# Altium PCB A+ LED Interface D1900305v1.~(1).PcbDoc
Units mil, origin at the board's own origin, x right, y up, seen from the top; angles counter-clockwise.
Board outline 2700 x 2000 mil, 4 copper layers (Top Layer, InternalPlane1, InternalPlane2, Bottom Layer); 19 components, 34 nets, 90 pads, 10 vias.
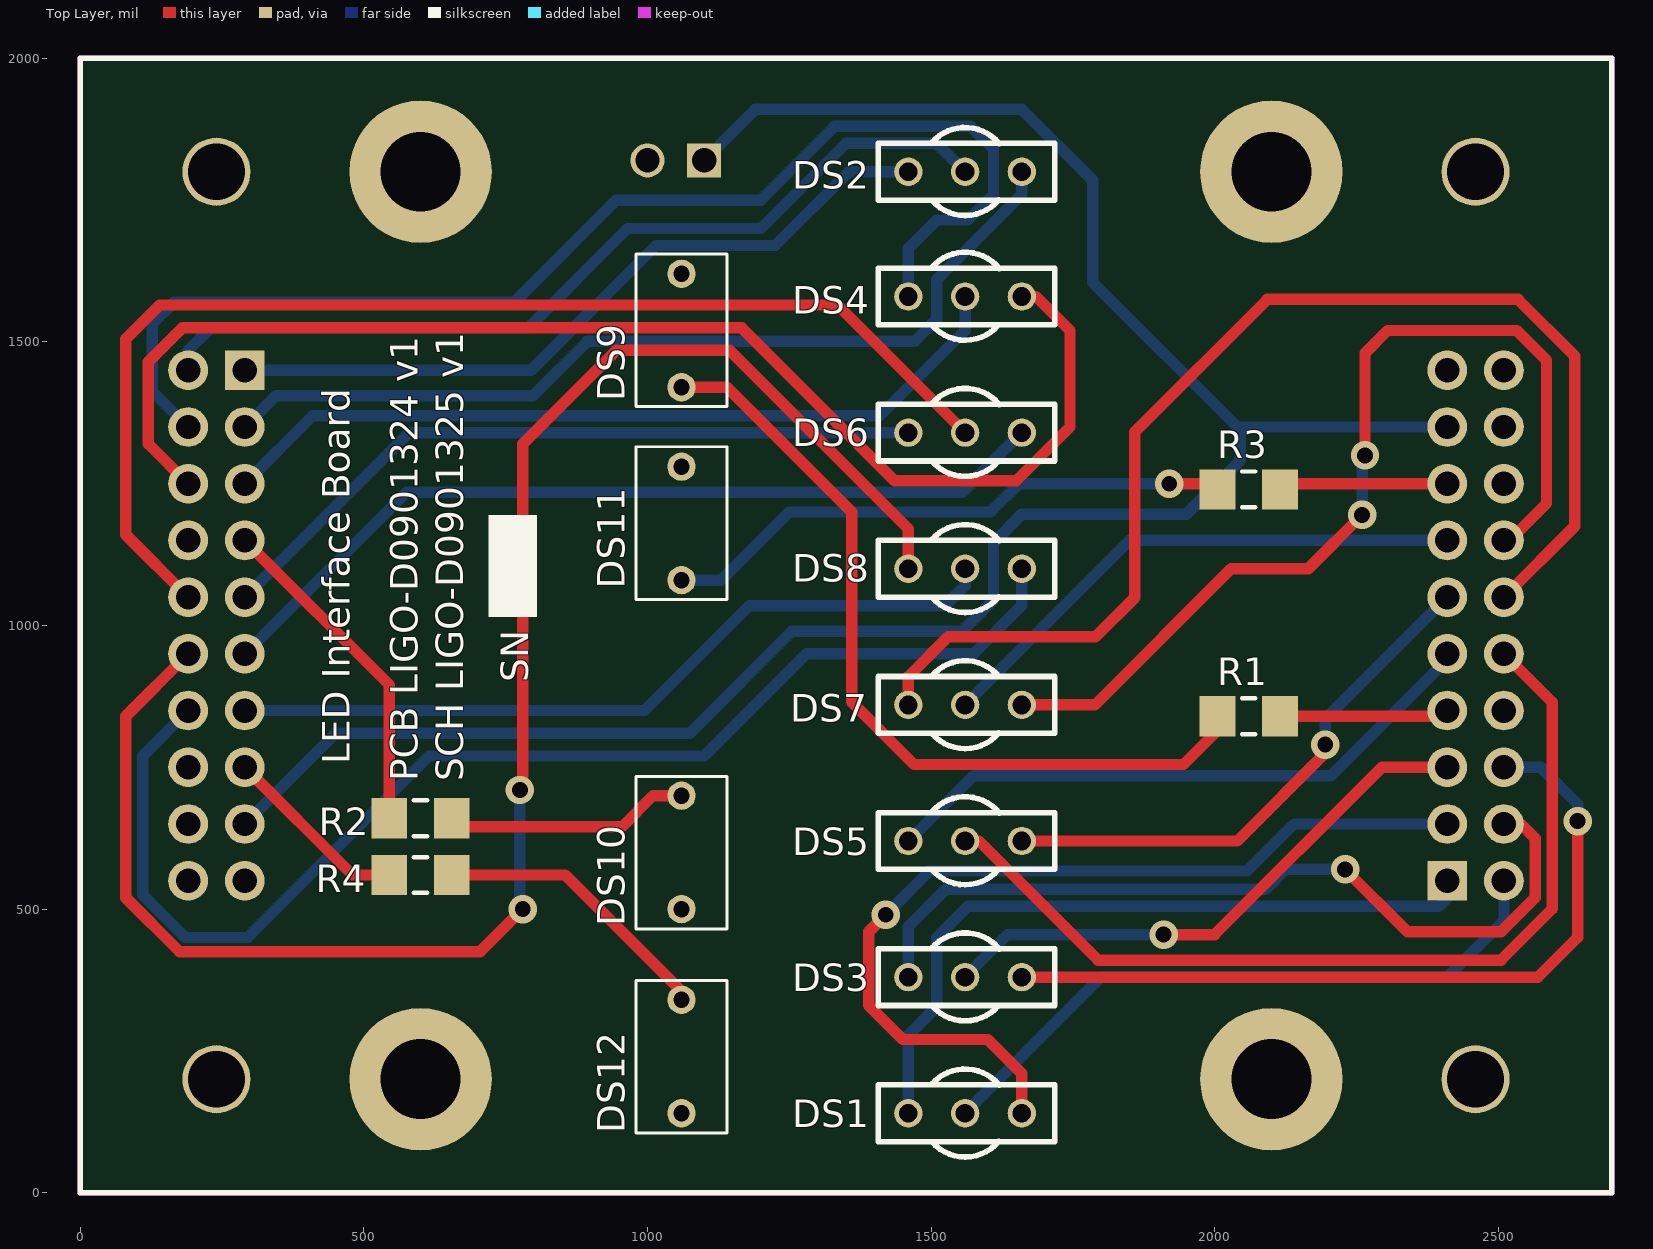
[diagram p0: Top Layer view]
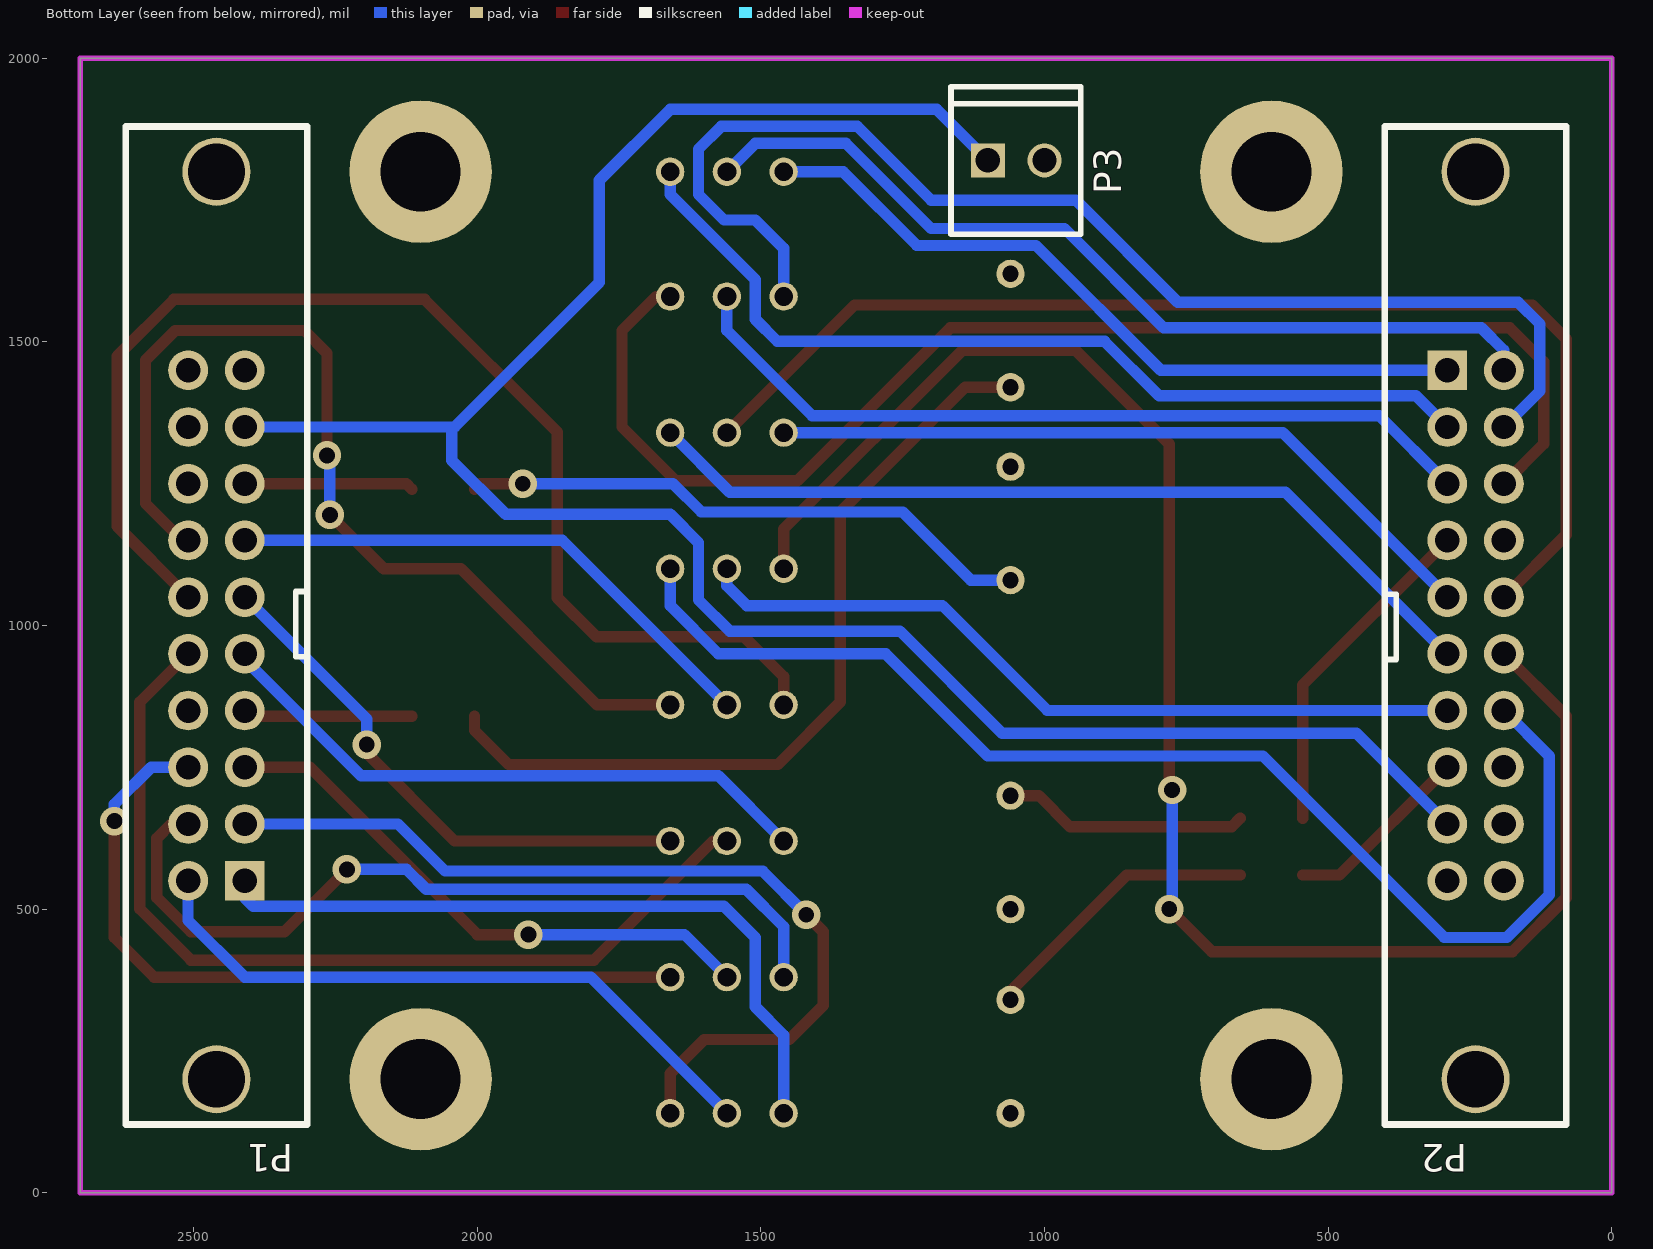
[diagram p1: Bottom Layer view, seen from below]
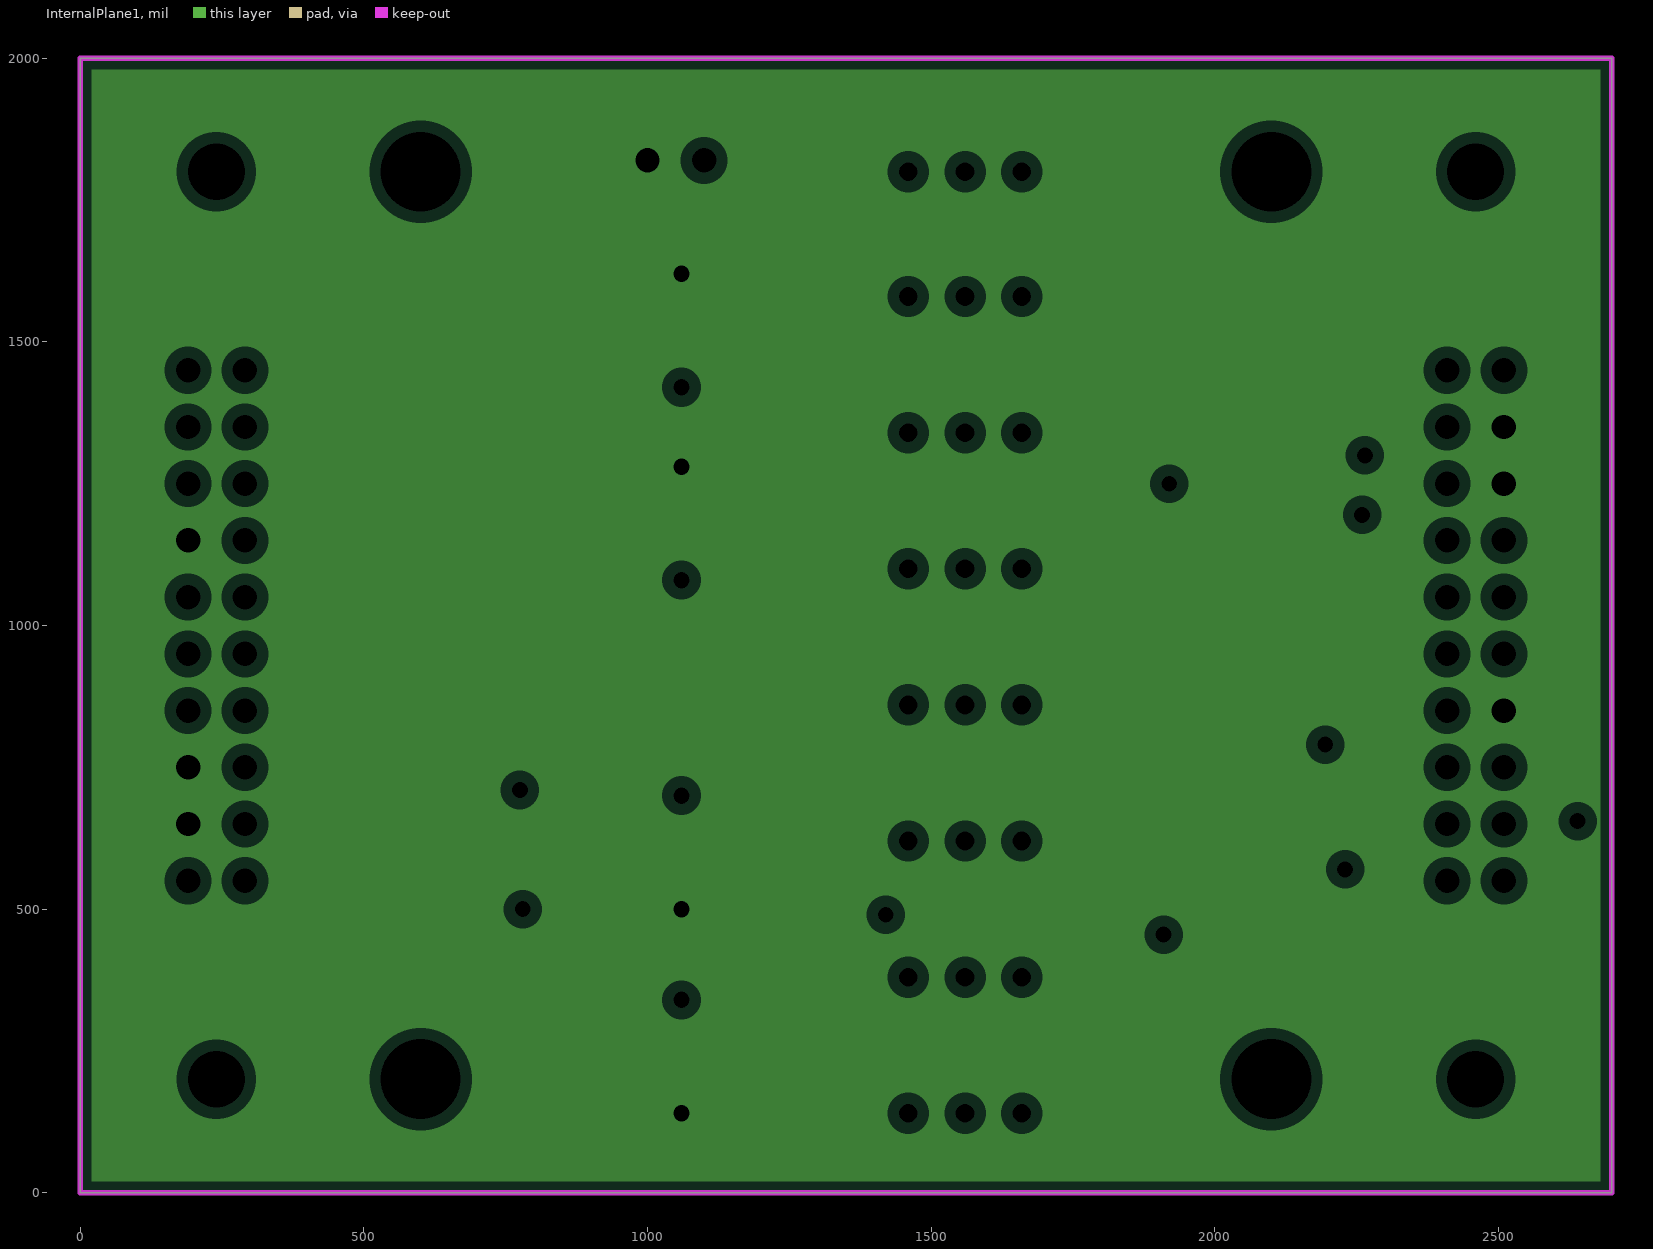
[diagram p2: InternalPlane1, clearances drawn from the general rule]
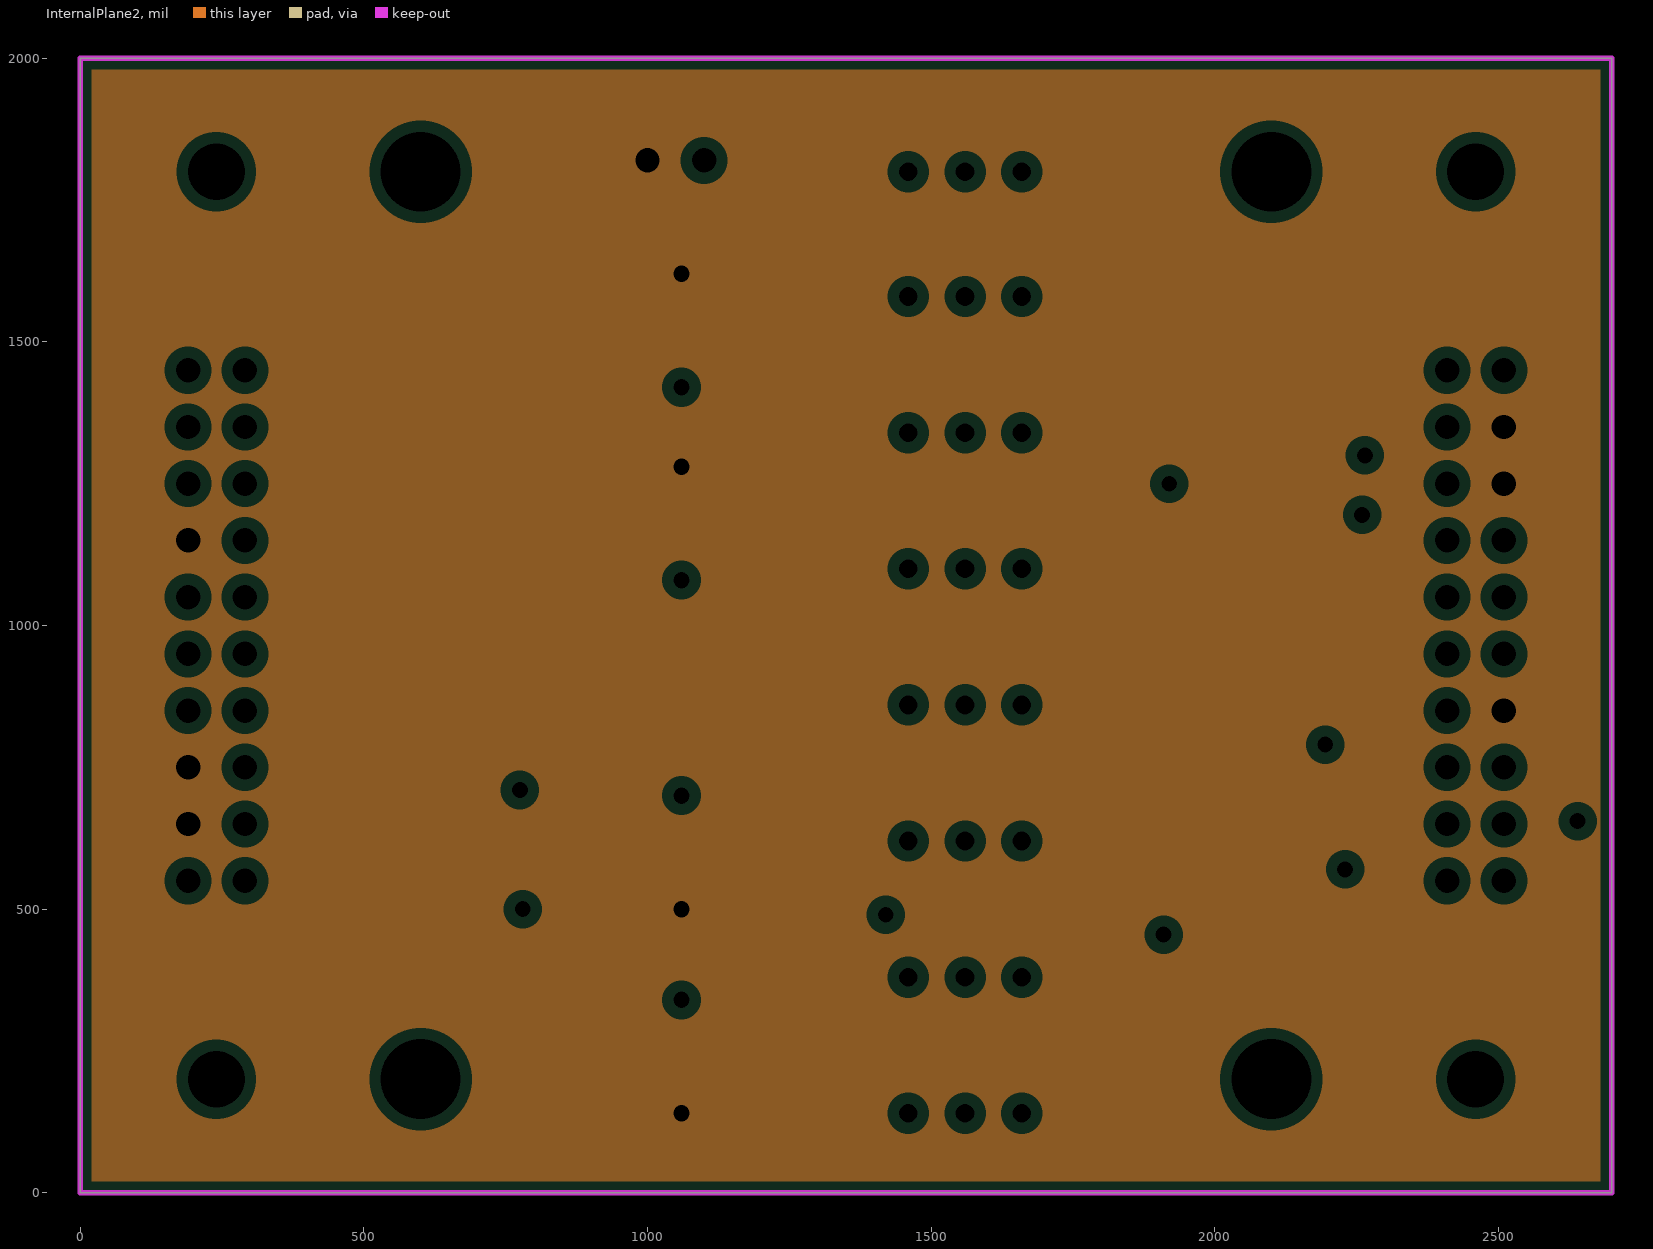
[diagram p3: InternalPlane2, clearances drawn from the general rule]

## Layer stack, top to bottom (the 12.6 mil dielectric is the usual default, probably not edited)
Top Solder: solder mask 0.4, Solder Resist, Dk 3.5
Top Layer: signal copper 1.4
Dielectric1: core 12.6, FR-4, Dk 4.8
InternalPlane1: plane copper 1.4
Dielectric2: prepreg 12.6, FR-4, Dk 4.8
InternalPlane2: plane copper 1.4
Dielectric3: core 12.6, FR-4, Dk 4.8
Bottom Layer: signal copper 1.4
Bottom Solder: solder mask 0.4, Solder Resist, Dk 3.5

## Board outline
0,0 2700,0 2700,2000 0,2000 0,0

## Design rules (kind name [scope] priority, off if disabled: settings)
Clearance [All] p1: gap=10 ignorepadtopadclearanceinfootprint=FALSE except(0: Arc-Hole Track-Hole SMDPad-Hole THPad-Hole Via-Hole Fill-Hole Poly-Hole Region-Hole Text-Hole)
FabricationTestPointUsage TestPointUsage [All] p1: valid=0 allowmultiple=FALSE
FabricationTestpoint Testpoint [All] p1: side=3 testpointundercomponent=TRUE minsize=40 maxsize=100 preferedsize=60 minholesize=0 maxholesize=40 preferedholesize=32 testpointgrid=1 allowsidetop=TRUE allowsidebottom=TRUE usegrid=TRUE gridtolerance=0.01
HoleSize [All] p1: absolutevalues=TRUE maxlimit=300 minlimit=1 maxpercent=80.000 minpercent=20.000
PlaneClearance [All] p1: clearance=20
PlaneConnect [All] p1: planeconnectstyle=Relief reliefexpansion=20 reliefentries=4 reliefconductorwidth=10 reliefairgap=10
PolygonConnect [All] p1: connectstyle=Relief reliefconductorwidth=10 reliefentries=4 polygonreliefangle="90 Angle" airgapwidth=10
RoomDefinition D0901325 [InComponentClass('D0901325')] p1: confinementstyle=ConfineIn formatcopy=TRUE lockcomponents=FALSE outline -40,-35 2735,-35 2735,2030 -40,2030
RoutingVias [All] p1: holewidth=28 width=50 viastyle="Through Hole" minholewidth=28 minwidth=50 maxholewidth=28 maxwidth=50
SolderMaskExpansion [All] p1: expansion=4
Width [All] p1: maxlimit=50 minlimit=10 preferedwidth=20 minimp=50.000000 maximp=50.000000 favimp=50.000000
25 further rules are at their usual default settings.

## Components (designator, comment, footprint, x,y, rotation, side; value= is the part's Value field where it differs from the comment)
DS1 "COM K LED" "COM_CATHODE LED" 1560,140 r90 top
DS2 "COM K LED" "COM_CATHODE LED" 1560,1800 r90 top
DS3 "COM K LED" "COM_CATHODE LED" 1560,380 r90 top
DS4 "COM K LED" "COM_CATHODE LED" 1560,1580 r90 top
DS5 "COM K LED" "COM_CATHODE LED" 1560,620 r90 top
DS6 "COM K LED" "COM_CATHODE LED" 1560,1340 r90 top
DS7 "COM K LED" "COM_CATHODE LED" 1560,860 r90 top
DS8 "COM K LED" "COM_CATHODE LED" 1560,1100 r90 top
DS9 "LED0" RED_led 1060,1420 r0 top
DS10 "LED0" RED_led 1060,700 r180 top
DS11 "LED0" RED_led 1060,1080 r0 top
DS12 "LED0" RED_led 1060,340 r180 top
P1 "Header 20" "IDC 20 _Vertical" 2460,1000 r90 bottom
P2 "Header 20" "IDC 20 _Vertical" 240,1000 r270 bottom
P3 "Molex 2 PIN" "2Pin_Molex 100 mil" 1100,1820 r180 bottom
R1 "1K" 3216[1206] 2060,840 r180 top
R2 "1K" 3216[1206] 600,660 r0 top
R3 "1K" 3216[1206] 2060,1240 r180 top
R4 "1K" 3216[1206] 600,560 r0 top

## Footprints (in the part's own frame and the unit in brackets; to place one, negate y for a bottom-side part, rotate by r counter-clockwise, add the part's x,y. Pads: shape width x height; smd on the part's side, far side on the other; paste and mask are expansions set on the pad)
"2Pin_Molex 100 mil" [mil]
  rect 60x60 hole 43: 1(0,0)
  round 60 hole 43: 2(100,0)
  silkscreen extent -65,-130 164,130
3216[1206] [mm] "Chip Resistor; Body 3.2 x 1.6 mm (LxW typ)"
  rect 1.6x1.8 smd: 1(-1.4,0) 2(1.4,0)
  silkscreen extent -0.3,-0.8 0.3,0.8
"COM_CATHODE LED" [mil]
  round 50 hole 33: 1(0,100) 2(0,0) 3(0,-100)
  silkscreen extent -77,-158 78,153
"IDC 20 _Vertical" [mil]
  round 120 hole 100: 0(-800,0) 0(800,0)
  rect 70x70 hole 43: 1(-450,-50)
  round 70 hole 43: 2(-450,50) 3(-350,-50) 4(-350,50) 5(-250,-50) 6(-250,50) 7(-150,-50) 8(-150,50) 9(-50,-50) 10(-50,50) 11(50,-50) 12(50,50) 13(150,-50) 14(150,50) 15(250,-50) 16(250,50) 17(350,-50) 18(350,50) 19(450,-50) 20(450,50)
  silkscreen extent -880,-160 880,160
RED_led [mil]
  round 50 hole 29: 1(0,0) 2(0,200)
  silkscreen extent -80,-34 80,235

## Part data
DS1 DS2 DS3 DS4 DS5 DS6 DS7 DS8: "Dual Colored LED/ Common Cathode"
DS9 DS10 DS11 DS12: "Typical INFRARED GaAs LED"
P1 P2: "Header, 20-Pin"
P3: library part "Header 2H", "Header, 2-Pin, Right Angle"
R1 R2 R3 R4: library part "Res Semi", "Semiconductor Resistor"

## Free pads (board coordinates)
  round 251 hole 141: 1(600,200) 2(2100,200) 3(2100,1800) 4(600,1800)

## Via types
v1: diameter 50, hole 28, Top Layer to Bottom Layer, 10 vias

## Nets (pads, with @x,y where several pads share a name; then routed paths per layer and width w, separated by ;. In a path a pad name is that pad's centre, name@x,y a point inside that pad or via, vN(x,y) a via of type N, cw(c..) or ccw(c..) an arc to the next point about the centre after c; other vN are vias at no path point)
GND: DS9.2 DS10.2 DS11.2 DS12.2 P1.8 P1.16 P1.18 P2.8 P2.16 P2.18 P3.2
NetDS1_1: DS1.1 P1.1 | length 1289.7
  Bottom Layer w20: DS1.1 1460,277.67 1510,327.67 1510,450 1565,505 2395,505 2410,520 P1.1
NetDS1_2: DS1.2 P1.2 | length 1160.8
  Bottom Layer w20: DS1.2 1800,380 2410,380 2510,480 P1.2
NetDS1_3: DS1.3 P1.3 | length 1618.4
  Top Layer w20: v1(1420,490) 1390,460 1390,330 1450,270 1600,270 1660,210 DS1.3
  Bottom Layer w20: v1(1420,490) 1497,567 2057,567 2140,650 P1.3
NetDS2_1: DS2.1 P2.1 | length 1315
  Bottom Layer w20: P2.1 795,1450 1015,1670 1225,1670 1355,1800 DS2.1
NetDS2_2: DS2.2 P2.2 | length 1576.9
  Bottom Layer w20: P2.2 190,1485 230,1525 790,1525 965,1700 1200,1700 1350,1850 1510,1850 DS2.2
NetDS2_3: DS2.3 P2.3 | length 1620.8
  Bottom Layer w20: P2.3 345,1405 798,1405 894,1501 1471,1501 1510,1540 1510,1610 1660,1760 DS2.3
NetDS3_1: DS3.1 P1.4 | length 1471.6
  Top Layer w20: v1(2230,570) 2340,460 2360,460 ; 2365,460 2505,460 2565,520 2565,625 2540,650 P1.4
  Bottom Layer w20: DS3.1 1460,469 1526,535 2090,535 2125,570 v1(2230,570)
NetDS3_2: DS3.2 P1.5 | length 1003.3
  Top Layer w20: v1(1910,455) 2000,455 2295,750 P1.5
  Bottom Layer w20: DS3.2 1635,455 v1(1910,455)
NetDS3_3: DS3.3 P1.6 | length 1400.9
  Top Layer w20: DS3.3 2570,380 2640,450 v1(2640,655)
  Bottom Layer w20: P1.6 2575,750 2640,685 v1(2640,655)
NetDS4_1: DS4.1 P2.4 | length 2206.5
  Bottom Layer w20: P2.4 126.64,1413.36 126.64,1531.64 165,1570 765,1570 945,1750 1200,1750 1330,1880 1570,1880 1610,1840 1610,1760 1565,1715 1510,1715 1460,1665 DS4.1
NetDS4_2: DS4.2 P2.5 | length 1441.8
  Bottom Layer w20: P2.5 410,1370 1410,1370 1560,1520 DS4.2
NetDS4_3: DS4.3 P2.6 | length 2324.9
  Top Layer w20: P2.6 120,1320 120,1465 180,1525 1166,1525 1436,1255 1650,1255 1745,1350 1745,1520 1685,1580 DS4.3
NetDS5_1: DS5.1 P1.9 | length 1092.5
  Bottom Layer w20: DS5.1 1575,735 2205,735 2410,940 P1.9
NetDS5_2: DS5.2 P1.10 | length 1644.5
  Top Layer w20: DS5.2 1584.38,620 1794.38,410 2505,410 2595,500 2595,865 P1.10
NetDS5_3: DS5.3 P1.11 | length 963.3
  Top Layer w20: DS5.3 2040,620 2195,775 v1(2195,790)
  Bottom Layer w20: v1(2195,790) 2195,835 P1.11
NetDS6_1: DS6.1 P2.9 | length 1290.1
  Bottom Layer w20: P2.9 580,1340 DS6.1
NetDS6_2: DS6.2 P2.10 | length 2098.6
  Top Layer w20: P2.10 80,1160 80,1505 140,1565 1335,1565 DS6.2
NetDS6_3: DS6.3 P2.11 | length 1531.5
  Bottom Layer w20: P2.11 575,1235 1555,1235 DS6.3
NetDS7_1: DS7.1 P1.12 | length 2189.7
  Top Layer w20: DS7.1 1460,910 1530,980 1790,980 1859.02,1049.02 1859.02,1341.02 2093,1575 2535,1575 2635,1475 2635,1175 P1.12
NetDS7_2: DS7.2 P1.13 | length 970.1
  Bottom Layer w20: DS7.2 1850,1150 P1.13
NetDS7_3: DS7.3 P1.14 | length 1752.6
  Top Layer w10: 1985,1060 1989,1060
  Top Layer w20: DS7.3 1789,860 2029,1100 2165,1100 v1(2260,1195) ; v1(2265,1300) 2265,1480 2305,1520 2532.57,1520 2585,1467.57 2585,1215 2520,1150 P1.14 P1.14@2510,1140
  Bottom Layer w20: v1(2260,1195) 2260,1295 v1(2265,1300)
NetDS8_1: DS8.1 P2.12 | length 3018.9
  Top Layer w20: P2.12 80,840 80,520 175,425 705,425 v1(780,500) ; v1(775,710) 780,715 780,1320 945,1485 1145,1485 1460,1170 DS8.1
  Bottom Layer w20: v1(775,710) 775,505 v1(780,500)
NetDS8_2: DS8.2 P2.13 | length 1391.1
  Bottom Layer w20: P2.13 995,850 1180,1035 1525,1035 1560,1070 DS8.2
NetDS8_3: DS8.3 P2.14 | length 2246.5
  Bottom Layer w20: P2.14 110,770 110,525 185,450 295,450 615,770 1100,770 1280,950 1575,950 1660,1035 DS8.3
NetDS9_1: DS9.1 R1.2 | length 1466.4
  Top Layer w20: DS9.1 1140,1420 1360,1200 1360,865.12 1470.12,755 1945,755 2004.88,814.88 R1.2
NetDS10_1: DS10.1 R2.2 | length 433.9
  Top Layer w20: R2.2 670.12,645 955,645 1010,700 DS10.1
NetDS11_1: DS11.1 R3.2 | length 1019.4
  Top Layer w20: v1(1920,1250) 1994.88,1250 R3.2
  Bottom Layer w20: DS11.1 1130,1080 1250,1200 1605,1200 1655,1250 v1(1920,1250)
NetDS12_1: DS12.1 R4.2 | length 504.8
  Top Layer w20: R4.2 855,560 1060,355 DS12.1
NetP1_7: P1.7 R1.1 | length 299
  Top Layer w20: R1.1 2400,840 P1.7
NetP1_15: P1.15 R3.1 | length 299
  Top Layer w20: R3.1 2125.12,1250 P1.15
NetP1_17: P1.17 P2.17 P3.1 | length 3813.4
  Bottom Layer w20: P2.17 450,810 1075,810 1255,990 1555,990 1610,1045 1610,1146 1660,1196 1950,1196 2045,1291 2045,1340 ; P3.1 1190,1910 1660,1910 1785,1785 1785,1605 2040,1350 P1.17
NetP2_7: P2.7 R2.1 | length 595.6
  Top Layer w20: P2.7 544.88,895.12 R2.1
NetP2_15: P2.15 R4.1 | length 333.6
  Top Layer w20: P2.15 480,560 R4.1
pads on no net: P1.0 P1.19 P1.20 P2.0 P2.19 P2.20

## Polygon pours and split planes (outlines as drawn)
GND on InternalPlane1 (split plane): 2679.9,20.1 20.1,20.1 20.1,1979.9 2679.9,1979.9
GND on InternalPlane2 (split plane): 2679.9,20.1 20.1,20.1 20.1,1979.9 2679.9,1979.9

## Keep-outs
Keep-Out Layer:
  the board outline again, w10

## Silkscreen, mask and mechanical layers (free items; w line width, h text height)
Top Overlay:
  region: 805,1015 805,1195 720,1195 720,1015
  lines w10: 0,0 2700,0 2700,2000 0,2000 0,0
  text "SN" at 790,900 h48 r90
  text "LED Interface Board" at 475,755 h48 r90
  text "PCB LIGO-D0901324 v1" at 595,725 h48 r90
  text "SCH LIGO-D0901325 v1" at 675,725 h48 r90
